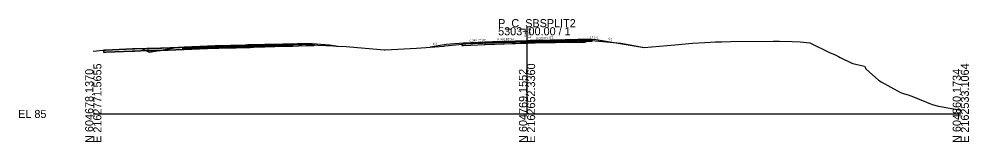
# Model space of a CAD drawing. Extents: x -26 to 1303, y -10 to 12033.
# Drawn here: x -25.7 to 302.8, y 11990.3 to 12032.8 of the extents above; entities that cross this region are included whole.
import ezdxf

# ---------------------------------------------------------------- set-up
doc = ezdxf.new("R2010")
doc.units = 0
for name, color, linetype in [('RD_GPK_XS_Cell', 7, 'Continuous'), ('RD_XS_Base', 7, 'Continuous'), ('RD_XS_ExGround', 7, 'Continuous'), ('RD_XS_ExPaveRet', 7, 'Continuous'), ('RD_XS_Greenside', 7, 'Continuous'), ('RD_XS_Pave', 7, 'Continuous'), ('RD_XS_PaveOvlay_CP', 7, 'Continuous'), ('RD_XS_TieSlope', 7, 'Continuous'), ('RD_XS_TX_Elev_EX', 7, 'Continuous'), ('RD_XS_TX_Elev_PR', 7, 'Continuous'), ('RD_XS_TX_ShdSlope', 7, 'Continuous'), ('RD_XS_TX_Slope', 7, 'Continuous')]:
    doc.layers.add(name, color=color, linetype=linetype)

msp = doc.modelspace()

# ---------------------------------------------------------------- linework, layer by layer
at = {"layer": 'RD_GPK_XS_Cell'}
for p, q in [((150, 12000), (150, 12030)), ((0, 12000), (150, 12000)), ((150, 12000), (300, 12000))]:
    msp.add_line(p, q, dxfattribs=at)
at = {"layer": 'RD_XS_Base'}
for p, q in [((138, 12024.62), (128, 12024.22)), ((136, 12024.54), (136, 12024.54)), ((150, 12024.95), (138, 12024.62)), ((138, 12024.12), (150, 12024.45)), ((150, 12024.95), (171.94, 12025.57)), ((150, 12024.45), (150, 12025.11)), ((150, 12025.11), (150, 12025.11)), ((150, 12025.11), (150, 12025.11)), ((150, 12025.11), (150, 12024.95)), ((172.44, 12025.08), (150, 12024.45)), ((150, 12024.95), (150, 12024.95)), ((150, 12024.45), (150, 12024.95)), ((150, 12024.95), (150, 12024.95)), ((150, 12024.95), (150, 12024.95)), ((150, 12024.45), (150, 12024.45)), ((162, 12025.29), (162, 12025.29)), ((162, 12025.29), (162, 12025.29)), ((162, 12024.79), (162, 12024.79)), ((162, 12024.79), (162, 12024.79)), ((171.94, 12025.57), (171.94, 12025.57)), ((172.44, 12025.58), (172.44, 12025.08)), ((172.44, 12025.55), (172.44, 12025.55)), ((31.33, 12022.77), (30.88, 12022.75)), ((30.88, 12022.75), (30.88, 12022.7)), ((30.88, 12022.7), (30.88, 12022.25)), ((30.88, 12022.25), (31.33, 12022.27)), ((31.38, 12022.77), (31.33, 12022.77)), ((31.33, 12022.27), (31.38, 12022.27)), ((42.13, 12023.2), (31.38, 12022.77)), ((31.38, 12022.27), (42.13, 12022.7)), ((43.38, 12023.25), (42.13, 12023.2)), ((42.13, 12022.7), (43.38, 12022.75)), ((54.2, 12023.53), (43.38, 12023.25)), ((43.38, 12022.75), (54.2, 12023.03)), ((55.38, 12023.56), (54.2, 12023.53)), ((54.2, 12023.03), (55.38, 12023.06)), ((55.38, 12023.56), (76.22, 12024.1)), ((55.38, 12023.06), (55.38, 12023.72)), ((55.38, 12023.72), (55.38, 12023.72)), ((55.38, 12023.72), (55.38, 12023.72)), ((55.38, 12023.72), (55.38, 12023.56)), ((76.22, 12023.6), (55.38, 12023.06)), ((55.38, 12023.56), (55.38, 12023.56)), ((55.38, 12023.06), (55.38, 12023.56)), ((55.38, 12023.56), (55.38, 12023.56)), ((55.38, 12023.56), (55.38, 12023.56)), ((55.38, 12023.06), (55.38, 12023.06)), ((75.72, 12024.09), (75.72, 12024.09)), ((76.22, 12024.1), (76.22, 12023.6)), ((76.22, 12024.07), (76.22, 12024.07)), ((128, 12024.22), (127.5, 12024.2)), ((127.5, 12024.2), (127.5, 12024.2)), ((127.5, 12024.2), (127.5, 12023.7)), ((127.5, 12023.7), (128, 12023.72)), ((128, 12024.22), (128, 12024.22)), ((128, 12023.72), (138, 12024.12)), ((128, 12023.72), (128, 12023.72)), ((136, 12024.04), (136, 12024.04))]:
    msp.add_line(p, q, dxfattribs=at)
at = {"layer": 'RD_XS_ExGround'}
msp.add_lwpolyline([(0, 12021.74), (3.34, 12022.04), (3.58, 12022.04), (3.7, 12022.06), (4.31, 12022.09), (8.64, 12022.27), (13.85, 12022.49), (14.12, 12022.49), (18.15, 12022.65), (18.78, 12022.68), (18.88, 12022.68), (19.96, 12022.6), (23.72, 12022.75), (36.53, 12023.24), (38.9, 12023.36), (41.9, 12023.5), (43.13, 12023.56), (47.4, 12023.66), (49.45, 12023.64), (50.68, 12023.7), (52.54, 12023.81), (53.44, 12023.88), (66.63, 12024.18), (68.92, 12024.24), (71.51, 12024.1), (77.63, 12023.79), (83.09, 12023.51), (84.09, 12023.47), (87.4, 12023.37), (99.29, 12022.32), (100.61, 12022.21), (100.91, 12022.22), (111.8, 12022.7), (115, 12023.03), (121.26, 12023.49), (121.35, 12023.5), (121.55, 12023.52), (130.08, 12024.33), (135.43, 12024.8), (138.9, 12024.93), (150.67, 12025.34), (150.75, 12025.34), (150.84, 12025.34), (151.06, 12025.35), (151.17, 12025.35), (152.76, 12025.39), (155.33, 12025.43), (158.77, 12025.5), (159.84, 12025.52), (166.95, 12025.59), (169.86, 12025.63), (170.42, 12025.64), (173.65, 12025.33), (182.41, 12024.51), (185.71, 12023.88), (190.56, 12022.95), (201.1, 12023.94), (207.21, 12024.5), (211.49, 12024.71), (215.16, 12024.89), (216.99, 12024.98), (217.37, 12024.98), (220.51, 12025.02), (235.17, 12025.12), (236.78, 12025.13), (237.29, 12025.12), (241.67, 12025.03), (244.48, 12024.89), (247.78, 12024.59), (254.83, 12021.19), (256.29, 12020.57), (257.67, 12019.82), (258.31, 12019.52), (262.36, 12017.58), (262.47, 12017.52), (262.66, 12017.48), (266.67, 12016.52), (267.3, 12015.51), (271.51, 12011.67), (272.48, 12011.16), (279.16, 12007.39), (280.54, 12006.96), (281.82, 12006.6), (283.63, 12005.94), (290.05, 12003.28), (292.24, 12002.66), (300, 12001.3)], dxfattribs=at)
at = {"layer": 'RD_XS_ExPaveRet'}
for points in [[(170.42, 12025.64), (170.42, 12025.64), (169.86, 12025.63), (166.95, 12025.59), (166.95, 12025.59), (159.84, 12025.52), (158.77, 12025.5), (158.77, 12025.5), (155.33, 12025.43), (155.33, 12025.43), (152.76, 12025.39), (152.76, 12025.39), (151.17, 12025.35), (151.17, 12025.35), (151.06, 12025.35), (150.84, 12025.34), (150.84, 12025.34), (150.75, 12025.34), (150.67, 12025.34), (150.67, 12025.34), (138.9, 12024.93), (138.9, 12024.93), (135.43, 12024.8), (135.43, 12024.8), (135.43, 12024.8), (135.43, 12024.8), (135.43, 12024.05), (135.43, 12024.05), (135.43, 12024.05), (138.9, 12024.18), (138.9, 12024.18), (150.67, 12024.59), (150.67, 12024.59), (150.75, 12024.59), (150.84, 12024.59), (150.84, 12024.59), (151.06, 12024.6), (151.17, 12024.6), (151.17, 12024.6), (152.76, 12024.64), (152.76, 12024.64), (155.33, 12024.68), (155.33, 12024.68), (158.77, 12024.75), (158.77, 12024.75), (159.84, 12024.77), (166.95, 12024.84), (166.95, 12024.84), (169.86, 12024.88), (170.42, 12024.89), (170.42, 12024.89), (170.42, 12024.89), (170.42, 12025.64), (170.42, 12025.64), (170.42, 12025.64)], [(170.42, 12025.64), (169.86, 12025.63), (166.95, 12025.59), (159.84, 12025.52), (158.77, 12025.5), (155.33, 12025.43), (152.76, 12025.39), (151.17, 12025.35), (151.06, 12025.35), (150.84, 12025.34), (150.75, 12025.34), (150.67, 12025.34), (138.9, 12024.93), (135.43, 12024.8), (135.43, 12024.8), (135.43, 12024.05), (135.43, 12024.05), (138.9, 12024.18), (150.67, 12024.59), (150.75, 12024.59), (150.84, 12024.59), (151.06, 12024.6), (151.17, 12024.6), (152.76, 12024.64), (155.33, 12024.68), (158.77, 12024.75), (159.84, 12024.77), (166.95, 12024.84), (169.86, 12024.88), (170.42, 12024.89), (170.42, 12025.64)], [(66.63, 12024.18), (68.91, 12024.24), (68.91, 12023.5), (68.91, 12023.49), (66.63, 12023.43), (66.36, 12023.42), (59.32, 12023.27), (53.54, 12023.14), (53.44, 12023.13), (53.43, 12023.13), (52.54, 12023.06), (52.52, 12023.06), (50.68, 12022.95), (50.65, 12022.95), (49.45, 12022.89), (49.44, 12022.89), (47.4, 12022.91), (43.32, 12022.82), (43.13, 12022.81), (41.91, 12022.75), (41.9, 12022.75), (39.05, 12022.62), (38.97, 12022.62), (38.95, 12022.61), (38.92, 12022.61), (36.51, 12022.49), (36.4, 12022.49), (23.19, 12021.98), (22.26, 12021.94), (19.96, 12021.85), (19.92, 12021.85), (19.22, 12021.9), (18.85, 12021.92), (18.47, 12021.91), (14.33, 12021.75), (13.88, 12021.74), (13.77, 12021.74), (13.53, 12021.73), (4.31, 12021.34), (3.7, 12021.31), (3.7, 12021.99), (3.7, 12022.06), (4.31, 12022.09), (13.53, 12022.48), (13.77, 12022.49), (13.88, 12022.49), (14.33, 12022.5), (18.47, 12022.66), (18.85, 12022.67), (19.22, 12022.65), (19.92, 12022.6), (19.96, 12022.6), (22.26, 12022.69), (23.19, 12022.73), (36.4, 12023.24), (36.51, 12023.24), (38.92, 12023.36), (38.95, 12023.36), (38.97, 12023.37), (39.05, 12023.37), (41.9, 12023.5), (41.91, 12023.5), (43.13, 12023.56), (43.32, 12023.57), (47.4, 12023.66), (49.44, 12023.64), (49.45, 12023.64), (50.65, 12023.7), (50.68, 12023.7), (52.52, 12023.81), (52.54, 12023.81), (53.43, 12023.88), (53.44, 12023.88), (53.54, 12023.89), (59.32, 12024.02), (66.36, 12024.17), (66.63, 12024.18)], [(66.36, 12024.17), (59.32, 12024.02), (53.54, 12023.89), (53.44, 12023.88), (53.43, 12023.88), (52.54, 12023.81), (52.52, 12023.81), (50.68, 12023.7), (50.65, 12023.7), (49.45, 12023.64), (49.44, 12023.64), (47.4, 12023.66), (43.32, 12023.57), (43.13, 12023.56), (41.91, 12023.5), (41.9, 12023.5), (39.05, 12023.37), (38.97, 12023.37), (38.95, 12023.36), (38.92, 12023.36), (36.51, 12023.24), (36.4, 12023.24), (23.19, 12022.73), (22.26, 12022.69), (19.96, 12022.6), (19.92, 12022.6), (19.22, 12022.65), (18.85, 12022.67), (18.47, 12022.66), (14.33, 12022.5), (13.88, 12022.49), (13.77, 12022.49), (13.53, 12022.48), (4.31, 12022.09), (3.7, 12022.06), (3.7, 12021.99), (3.7, 12021.31), (4.31, 12021.34), (13.53, 12021.73), (13.77, 12021.74), (13.88, 12021.74), (14.33, 12021.75), (18.47, 12021.91), (18.85, 12021.92), (19.22, 12021.9), (19.92, 12021.85), (19.96, 12021.85), (22.26, 12021.94), (23.19, 12021.98), (36.4, 12022.49), (36.51, 12022.49), (38.92, 12022.61), (38.95, 12022.61), (38.97, 12022.62), (39.05, 12022.62), (41.9, 12022.75), (41.91, 12022.75), (43.13, 12022.81), (43.32, 12022.82), (47.4, 12022.91), (49.44, 12022.89), (49.45, 12022.89), (50.65, 12022.95), (50.68, 12022.95), (52.52, 12023.06), (52.54, 12023.06), (53.43, 12023.13), (53.44, 12023.13), (53.54, 12023.14), (59.32, 12023.27), (66.36, 12023.42), (66.63, 12023.43), (68.91, 12023.49), (68.91, 12023.5), (68.91, 12024.24), (66.63, 12024.18), (66.36, 12024.17)]]:
    msp.add_lwpolyline(points, dxfattribs=at)
at = {"layer": 'RD_XS_Greenside'}
for p, q in [((173.94, 12025.73), (190.49, 12022.97)), ((19.38, 12021.26), (16.78, 12022.56)), ((29.38, 12022.93), (19.38, 12021.26)), ((81.72, 12023.93), (84.53, 12023.46)), ((122, 12024.05), (116.52, 12023.14))]:
    msp.add_line(p, q, dxfattribs=at)
at = {"layer": 'RD_XS_Pave'}
for p, q in [((75.72, 12024.41), (55.38, 12023.88)), ((75.72, 12024.25), (75.72, 12024.41)), ((75.72, 12024.41), (75.72, 12024.41)), ((138, 12024.93), (128, 12024.53)), ((128, 12024.38), (138, 12024.78)), ((138, 12024.78), (128, 12024.38)), ((128, 12024.22), (138, 12024.62)), ((128, 12024.53), (128, 12024.53)), ((128, 12024.53), (128, 12024.38)), ((128, 12024.38), (128, 12024.38)), ((128, 12024.38), (128, 12024.22)), ((136, 12024.85), (136, 12024.85)), ((136, 12024.7), (136, 12024.7)), ((136, 12024.7), (136, 12024.7)), ((136, 12024.54), (136, 12024.54)), ((150, 12025.27), (138, 12024.93)), ((138, 12024.78), (150, 12025.11)), ((150, 12025.11), (138, 12024.78)), ((138, 12024.62), (150, 12024.95)), ((171.94, 12025.89), (150, 12025.27)), ((171.94, 12025.73), (150, 12025.11)), ((150, 12025.11), (171.94, 12025.73)), ((150, 12024.95), (172.44, 12025.58)), ((150, 12025.27), (150, 12025.27)), ((150, 12025.11), (150, 12025.11)), ((150, 12025.11), (150, 12025.11)), ((150, 12025.11), (150, 12024.95)), ((150, 12025.11), (150, 12025.11)), ((150, 12024.95), (150, 12025.11)), ((150, 12025.11), (150, 12025.11)), ((150, 12025.11), (150, 12025.11)), ((150, 12024.95), (150, 12024.95)), ((150, 12024.95), (150, 12024.95)), ((162, 12025.61), (162, 12025.61)), ((162, 12025.61), (162, 12025.61)), ((162, 12025.45), (162, 12025.45)), ((162, 12025.45), (162, 12025.45)), ((162, 12025.45), (162, 12025.45)), ((162, 12025.45), (162, 12025.45)), ((162, 12025.29), (162, 12025.29)), ((162, 12025.29), (162, 12025.29)), ((171.94, 12025.73), (171.94, 12025.89)), ((171.94, 12025.89), (171.94, 12025.89)), ((171.94, 12025.57), (171.94, 12025.73)), ((171.94, 12025.73), (171.94, 12025.73)), ((42.13, 12023.52), (31.38, 12023.09)), ((31.38, 12022.93), (42.13, 12023.36)), ((42.13, 12023.36), (31.38, 12022.93)), ((31.38, 12022.77), (42.13, 12023.2)), ((31.38, 12023.09), (31.38, 12023.07)), ((31.38, 12023.07), (31.38, 12022.93)), ((31.38, 12022.93), (31.38, 12022.91)), ((31.38, 12022.91), (31.38, 12022.77)), ((43.38, 12023.57), (42.13, 12023.52)), ((42.13, 12023.36), (43.38, 12023.41)), ((43.38, 12023.41), (42.13, 12023.36)), ((42.13, 12023.2), (43.38, 12023.25)), ((54.2, 12023.85), (43.38, 12023.57)), ((43.38, 12023.41), (54.2, 12023.69)), ((54.2, 12023.69), (43.38, 12023.41)), ((43.38, 12023.25), (54.2, 12023.53)), ((55.38, 12023.88), (54.2, 12023.85)), ((54.2, 12023.69), (55.38, 12023.72)), ((55.38, 12023.72), (54.2, 12023.69)), ((54.2, 12023.53), (55.38, 12023.56)), ((75.72, 12024.25), (55.38, 12023.72)), ((55.38, 12023.72), (75.72, 12024.25)), ((55.38, 12023.56), (75.72, 12024.09)), ((55.38, 12023.88), (55.38, 12023.88)), ((55.38, 12023.72), (55.38, 12023.72)), ((55.38, 12023.72), (55.38, 12023.72)), ((55.38, 12023.72), (55.38, 12023.56)), ((55.38, 12023.72), (55.38, 12023.72)), ((55.38, 12023.56), (55.38, 12023.72)), ((55.38, 12023.72), (55.38, 12023.72)), ((55.38, 12023.72), (55.38, 12023.72)), ((55.38, 12023.56), (55.38, 12023.56)), ((55.38, 12023.56), (55.38, 12023.56)), ((75.72, 12024.09), (75.72, 12024.25)), ((75.72, 12024.25), (75.72, 12024.25))]:
    msp.add_line(p, q, dxfattribs=at)
at = {"layer": 'RD_XS_PaveOvlay_CP'}
for p, q in [((75.72, 12024.41), (55.38, 12023.88)), ((138, 12024.93), (128, 12024.53)), ((136, 12024.85), (136, 12024.85)), ((150, 12025.27), (138, 12024.93)), ((162, 12025.61), (150, 12025.27)), ((150, 12025.27), (150, 12025.27)), ((162, 12025.61), (162, 12025.61)), ((162, 12025.61), (162, 12025.61)), ((42.13, 12023.52), (31.38, 12023.09)), ((43.38, 12023.57), (42.13, 12023.52)), ((54.2, 12023.85), (43.38, 12023.57)), ((55.38, 12023.88), (54.2, 12023.85)), ((55.38, 12023.88), (55.38, 12023.88))]:
    msp.add_line(p, q, dxfattribs=at)
at = {"layer": 'RD_XS_TieSlope'}
for p, q in [((75.72, 12024.41), (81.72, 12023.93)), ((128, 12024.53), (122, 12024.05)), ((171.94, 12025.89), (173.94, 12025.73)), ((31.38, 12023.09), (29.38, 12022.93))]:
    msp.add_line(p, q, dxfattribs=at)

# ---------------------------------------------------------------- texts
at = {"layer": 'RD_GPK_XS_Cell'}
for s, p in [('P_C_SBSPLIT2', (140, 12030)), ('5303+00.00 / 1', (140, 12027.2)), ('EL 85', (-26, 11998.6))]:
    msp.add_text(s, height=2.8, dxfattribs=at).set_placement(p)
for s, p in [('N 604678.1370', (0, 11990)), ('E 2162771.5655', (2.8, 11990)), ('N 604769.1552', (150, 11990)), ('E 2162652.3360', (152.8, 11990)), ('N 604860.1734', (300, 11990)), ('E 2162533.1064', (302.8, 11990))]:
    msp.add_text(s, height=2.8, rotation=90, dxfattribs=at).set_placement(p)
at = {"layer": 'RD_XS_TX_Elev_EX'}
msp.add_text('110.32', height=0.6, rotation=90, dxfattribs=at).set_placement((149.68, 12026.53))
at = {"layer": 'RD_XS_TX_Elev_PR'}
msp.add_text('110.27', height=1, rotation=90, dxfattribs=at).set_placement((151.39, 12026.16))
at = {"layer": 'RD_XS_TX_ShdSlope'}
msp.add_text('12.5:1', height=0.75, rotation=355.4261, dxfattribs=at).set_placement((171.69, 12026.18))
at = {"layer": 'RD_XS_TX_Slope'}
for s, rotation, p in [('6:1', 9.4623, (117.5, 12023.81)), ('0.040 FT./FT.', 2.2906, (130.15, 12024.99)), ('0.030 FT./FT.', 1.7184, (139.8, 12025.4)), ('0.030 FT./FT.', 1.7184, (153.16, 12025.78)), ('6:1', 350.5358, (178.07, 12025.66))]:
    msp.add_text(s, height=0.75, rotation=rotation, dxfattribs=at).set_placement(p)

doc.saveas('drawing.dxf')
